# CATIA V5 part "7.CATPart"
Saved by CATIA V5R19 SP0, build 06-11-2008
Part number: 7
Bounding box of the stored display mesh (mm): x -145 to -93, y -51.576 to 494.405, z -91.92 to 184.638
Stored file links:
  G:\EU_thinkMotion\CFAO_2010\MMS_groupe3\MMS_groupe3\A reprendre\bblot\BLOT\7.CATPart
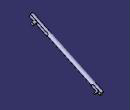
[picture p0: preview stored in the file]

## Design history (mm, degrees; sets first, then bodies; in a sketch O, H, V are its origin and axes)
Body1 (main body)
  Line1: stored without definition
  DatumPoint1
  Plane1: type Normal, Curve Line1, RefPoint DatumPoint1
  Line2: stored without definition
  DatumCurve1
  Sketch1 on Plane1, origin (0, 412.4062, -193.0412), H (1, 0, 0), V (0, 0.4239, 0.9057)
    circle A1 centre (-130, 135.8535) radius 15
    point P1 (-130, 135.8535)
    reference projected line E1 through (0, 135.8535) direction (1, 0) from Line2
    reference projected line E2 (-120, 175.8535) -> (-120, 118.8959) from edge of DatumCurve1
    radius A1 = 15
    distance E2 P1 = 10
    coincidence: P1 E1
  Line3: stored without definition
  Point1: stored without definition
  Point2: stored without definition
  Plane2: type Normal, Curve Line3, RefPoint Point2
  Pad1: profile Sketch1, direction (0, -0.9057, 0.4239), up to Plane2
  DatumCurve2
  Sketch2 on end face of Pad1, origin (0, -57.5938, 26.9588), H (1, 0, 0), V (0, 0.4239, 0.9057)
    line L1 (-140, 155.8535) -> (-120, 155.8535)
    line L2 (-120, 155.8535) -> (-120, 115.8535)
    line L3 (-120, 115.8535) -> (-140, 115.8535)
    line L4 (-140, 115.8535) -> (-140, 155.8535)
    axis line L5 (-130, 155.8535) -> (-130, 115.8535)
    point P5 (-130, 155.8535)
    point P6 (-130, 115.8535)
    reference projected line E1 (-120, 175.8535) -> (-120, 118.8959) from edge of DatumCurve2
    point P7 (-130, 135.8535)
    reference projected circle E2 centre (-130, 135.8535) radius 15 from edge [face of Pad1 from Sketch1.A1 | end face of Pad1]
    reference projected circle E3 centre (-130, 135.8535) radius 15 from edge [face of Pad1 from Sketch1.A1 | end face of Pad1]
    line L6 (-150, 160.8535) -> (-110, 160.8535)
    line L7 (-110, 160.8535) -> (-110, 110.8535)
    line L8 (-110, 110.8535) -> (-150, 110.8535)
    line L9 (-150, 110.8535) -> (-150, 160.8535)
    reference projected circle E4 centre (-130, 135.8535) radius 15 from edge [face of Pad1 from Sketch1.A1 | end face of Pad1]
    reference projected circle E5 centre (-130, 135.8535) radius 15 from edge [face of Pad1 from Sketch1.A1 | end face of Pad1]
    distance E3 L1 = 5
    distance L1 L6 = 5
    distance E4 L9 = 5
    distance E5 L7 = 5
    distance L3 L8 = 5
    horizontal: L1 H, L3 H, L6 H, L8 H
    vertical: L2 V, L4 V, L5 V, L7 V, L9 V
    coincidence: P5 L1, P6 L3, L2 E1, P7 L5
    midpoint: P5 L1, P7 L5
    concentricity: P7 E2
  Pocket1: profile Sketch2, direction (0, 0.9057, -0.4239), length 100
  Sketch3 on end face of Pad1, origin (0, -57.5938, 26.9588), H (1, 0, 0), V (0, 0.4239, 0.9057)
    arc A1 centre (-130, 135.8535) radius 15 from (-140, 124.6732) to (-120, 124.6732) ccw
    line L1 (-140, 147.0339) -> (-140, 124.6732)
    line L2 (-120, 147.0339) -> (-120, 124.6732)
    point P4 (-120, 147.0339)
    reference projected line E1 (-120, 115.8535) -> (-120, 155.8535) from edge [face of Pocket1 from Sketch2.L2 | end face of Pad1]
    reference projected circle E2 centre (-130, 135.8535) radius 15 from edge [face of Pad1 from Sketch1.A1 | end face of Pad1]
    reference projected line E3 (-140, 155.8535) -> (-140, 115.8535) from edge [face of Pocket1 from Sketch2.L4 | end face of Pad1]
    arc A2 centre (-130, 135.8535) radius 15 from (-120, 147.0339) to (-140, 147.0339) ccw
    vertical: L1 V, L2 V
    coincidence: P4 A1, L2 E1, A1 E2, L1 E3, A1 A2
  Pad2: profile Sketch3, direction (0, -0.9057, 0.4239), length 50
  DatumCurve3
  DatumSurface1
  Sketch4 on face of Pad2, origin (-120, 0, 0), H (0, 1, 0), V (0, 0, 1)
    circle A1 centre (0, 150) radius 10
    reference projected circle E1 centre (0, 150) radius 10 from edge of DatumCurve3
    coincidence: A1 E1
  Pad3: profile Sketch4, direction (1, 0, 0), up to face of DatumSurface1, offset 7
  Sketch5 on start face of Pad1, origin (0, 412.4062, -193.0412), H (-1, 0, 0), V (0, 0.4239, 0.9057)
    line L1 (120, 155.8535) -> (140, 155.8535)
    line L2 (140, 155.8535) -> (140, 115.8535)
    line L3 (140, 115.8535) -> (120, 115.8535)
    line L4 (120, 115.8535) -> (120, 155.8535)
    axis line L5 (130, 155.8535) -> (130, 115.8535)
    point P5 (130, 155.8535)
    point P6 (130, 115.8535)
    reference intersected line E1 through (120, 0) direction (0, 1) from face of Pad2
    point P7 (130, 135.8535)
    reference projected circle E2 centre (130, 135.8535) radius 15 from edge [start face of Pad1 | face of Pad1 from Sketch1.A1]
    reference projected circle E3 centre (130, 135.8535) radius 15 from edge [start face of Pad1 | face of Pad1 from Sketch1.A1]
    line L6 (110, 160.8535) -> (150, 160.8535)
    line L7 (150, 160.8535) -> (150, 110.8535)
    line L8 (150, 110.8535) -> (110, 110.8535)
    line L9 (110, 110.8535) -> (110, 160.8535)
    reference projected circle E4 centre (130, 135.8535) radius 15 from edge [start face of Pad1 | face of Pad1 from Sketch1.A1]
    reference projected circle E5 centre (130, 135.8535) radius 15 from edge [start face of Pad1 | face of Pad1 from Sketch1.A1]
    distance E3 L1 = 5
    distance E4 L7 = 5
    distance L1 L6 = 5
    distance L8 L3 = 5
    distance E5 L9 = 5
    horizontal: L1 H, L3 H, L6 H, L8 H
    vertical: L2 V, L4 V, L5 V, L7 V, L9 V
    midpoint: P5 L1, P6 L3, P7 L5
    coincidence: L4 E1, P7 L5
    concentricity: P7 E2
  Pocket2: profile Sketch5, direction (0, -0.9057, 0.4239), length 50
  Sketch6 on start face of Pad1, origin (0, 412.4062, -193.0412), H (-1, 0, 0), V (0, 0.4239, 0.9057)
    arc A1 centre (130, 135.8535) radius 15 from (140, 147.0339) to (120, 147.0339) ccw
    line L1 (120, 147.0339) -> (120, 124.6732)
    point P3 (120, 124.6732)
    line L2 (140, 147.0339) -> (140, 124.6732)
    reference projected line E1 (140, 115.8535) -> (140, 155.8535) from edge [face of Pocket2 from Sketch5.L2 | start face of Pad1]
    reference intersected line E2 (120, 105.8535) -> (120, 165.8535) from face of Pocket2 from Sketch5.L4
    reference projected circle E3 centre (130, 135.8535) radius 15 from edge [start face of Pad1 | face of Pad2]
    arc A2 centre (130, 135.8535) radius 15 from (120, 124.6732) to (140, 124.6732) ccw
    coincidence: P3 A1, L2 E1, L1 E2, A1 E3, A1 A2
    vertical: L1 V, L2 V
  Pad4: profile Sketch6, direction (0, 0.9057, -0.4239), length 20
  DatumCurve4
  DatumSurface2
  Plane3: stored without definition
  Sketch7 on face of Pad4, origin (-120, 0, 0), H (0, 1, 0), V (0, 0, 1)
    circle A1 centre (470, -70) radius 5
    reference projected circle E1 centre (470, -70) radius 5 from edge of DatumCurve4
    coincidence: A1 E1
  Pad5: profile Sketch7, direction (1, 0, 0), up to face of DatumSurface2, offset 5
